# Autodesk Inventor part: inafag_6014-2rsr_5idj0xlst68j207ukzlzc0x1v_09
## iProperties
Shininess: 64.0
Angle Display Precision: 2
Document Length Units: 11269
Document Angle Units: 11279
Document Time Units: 11290
Document Mass Units: 11283
Document Length Units Precision: 3
Document Angle Units Precision: 2
Compacted: True
Created: 2008-08
Part Number: inafag_6014-2rsr_5idj0xlst68j207ukzlzc0x1v_09
Document SubType Name: Modeling
Designer: tpomodeler
Density: 0.0
Volumn: 0.0
Area: 0.0
PropertySet Name: Model Information
Control State: 0
Master: False
Checked Out: False
Author: tpomodeler
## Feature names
1. inafag_6014-2rsr_5idj0xlst68j207ukzlzc0x1v
